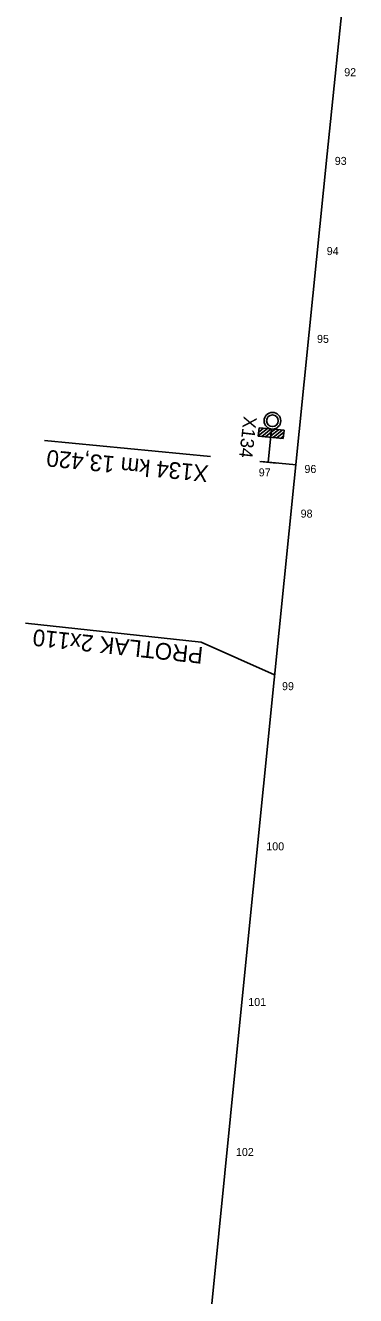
# Model space of a CAD drawing. Extents: x -743397 to -742769, y -1127804 to -1126284.
# Drawn here: x -743366.8 to -743317.3, y -1127613.8 to -1127423.3 of the extents above; entities that cross this region are included whole.
import ezdxf

# ---------------------------------------------------------------- set-up
doc = ezdxf.new("R2010")
doc.units = 0
for name, color, linetype in [('_Zabezpečovací zařízení', 7, 'Continuous'), ('_Zabezpečovací zařízení_trasa', 7, 'Continuous'), ('křížky', 7, 'Continuous'), ('Nový stav', 7, 'Continuous'), ('Vrstva 60', 7, 'Continuous')]:
    doc.layers.add(name, color=color, linetype=linetype)

# ---------------------------------------------------------------- blocks, each defined once
blk = doc.blocks.new('POINT_DISPLAY')
blk.add_line((0, 0), (0, 0))

msp = doc.modelspace()

# ---------------------------------------------------------------- linework, layer by layer
at = {"layer": '_Zabezpečovací zařízení'}
for p, q in [((-743331.88, -1127484.91), (-743331.75, -1127483.67)), ((-743331.88, -1127484.9), (-743330.52, -1127483.8)), ((-743331.82, -1127484.34), (-743331.08, -1127483.74)), ((-743331.76, -1127483.78), (-743331.64, -1127483.68)), ((-743331.75, -1127483.67), (-743328.02, -1127484.05)), ((-743331.34, -1127484.97), (-743329.96, -1127483.85)), ((-743330.4, -1127488.84), (-743329.89, -1127483.86)), ((-743328.15, -1127485.3), (-743331.88, -1127484.91)), ((-743330.78, -1127485.03), (-743329.94, -1127484.34)), ((-743330.22, -1127485.08), (-743330, -1127484.9)), ((-743330, -1127484.9), (-743328.85, -1127483.97)), ((-743329.94, -1127484.34), (-743329.41, -1127483.91)), ((-743329.66, -1127485.14), (-743328.29, -1127484.03)), ((-743329.1, -1127485.2), (-743328.05, -1127484.35)), ((-743328.54, -1127485.26), (-743328.11, -1127484.91)), ((-743328.02, -1127484.05), (-743328.15, -1127485.3)), ((-743329.16, -1127488.96), (-743331.64, -1127488.71))]:
    msp.add_line(p, q, dxfattribs=at)
for radius in [1.25, 0.875]:
    msp.add_circle((-743329.76, -1127482.62), radius, dxfattribs=at)
at = {"layer": '_Zabezpečovací zařízení_trasa'}
for points in [[(-743318.79, -1127415.84), (-743321.57, -1127442.6), (-743324.27, -1127469.35), (-743329.51, -1127521.46), (-743334.23, -1127568.82), (-743338.71, -1127613.56), (-743341.47, -1127641), (-743342.85, -1127654.73), (-743344.22, -1127668.45), (-743346.84, -1127694.61), (-743348.17, -1127707.68), (-743349.5, -1127720.75), (-743351.96, -1127744.53), (-743354.76, -1127768.22), (-743358.32, -1127790.48), (-743359.2, -1127794.79), (-743358.15, -1127794.97)], [(-743331.4, -1127488.73), (-743326.22, -1127489.25)]]:
    msp.add_lwpolyline(points, dxfattribs=at)
at = {"layer": 'Nový stav'}
for p, q in [((-743339.05, -1127488), (-743363.93, -1127485.56)), ((-743339.05, -1127488), (-743363.93, -1127485.56)), ((-743340.45, -1127515.81), (-743366.81, -1127512.98)), ((-743340.45, -1127515.81), (-743366.81, -1127512.98)), ((-743329.44, -1127520.71), (-743340.45, -1127515.81)), ((-743329.44, -1127520.71), (-743340.45, -1127515.81))]:
    msp.add_line(p, q, dxfattribs=at)
at = {"layer": 'Vrstva 60'}
for p, q in [((-743320.18, -1127429.22), (-743320.18, -1127429.22)), ((-743321.57, -1127442.6), (-743321.57, -1127442.6)), ((-743322.92, -1127455.97), (-743322.92, -1127455.97)), ((-743324.27, -1127469.35), (-743324.27, -1127469.35)), ((-743330.4, -1127488.84), (-743330.4, -1127488.84)), ((-743326.22, -1127489.25), (-743326.22, -1127489.25)), ((-743326.89, -1127495.41), (-743326.89, -1127495.41)), ((-743329.51, -1127521.46), (-743329.51, -1127521.46)), ((-743331.87, -1127545.14), (-743331.87, -1127545.14)), ((-743334.23, -1127568.82), (-743334.23, -1127568.82)), ((-743336.47, -1127591.19), (-743336.47, -1127591.19)), ((-743338.71, -1127613.56), (-743338.71, -1127613.56))]:
    msp.add_line(p, q, dxfattribs=at)

# ---------------------------------------------------------------- block references
at = {"layer": 'křížky', "xscale": 10, "yscale": 10, "rotation": 61.14491455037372}
for p in [(-743320.18, -1127429.22), (-743321.57, -1127442.6), (-743322.92, -1127455.97), (-743324.27, -1127469.35), (-743330.4, -1127488.84), (-743326.22, -1127489.25), (-743326.89, -1127495.41), (-743329.51, -1127521.46), (-743331.87, -1127545.14), (-743334.23, -1127568.82), (-743336.47, -1127591.19), (-743338.71, -1127613.56)]:
    msp.add_blockref('POINT_DISPLAY', p, dxfattribs=at)

# ---------------------------------------------------------------- texts
at = {"layer": '_Zabezpečovací zařízení'}
msp.add_text('X134', height=2, rotation=263.5157, dxfattribs=at).set_placement((-743334.07, -1127481.88))
at = {"layer": 'Nový stav'}
for s, rotation, p in [('X134 km 13,420', 174.395, (-743339.28, -1127489.34)), ('X134 km 13,420', 174.395, (-743339.28, -1127489.34)), ('PROTLAK 2x110', 173.8668, (-743340.06, -1127516.59)), ('PROTLAK 2x110', 173.8668, (-743340.06, -1127516.59))]:
    msp.add_text(s, height=2.5, rotation=rotation, dxfattribs=at).set_placement(p)
at = {"layer": 'Vrstva 60'}
for s, p in [('92', (-743318.99, -1127430.95)), ('93', (-743320.41, -1127444.25)), ('94', (-743321.61, -1127457.77)), ('95', (-743323.07, -1127470.94)), ('96', (-743324.96, -1127490.45)), ('97', (-743331.81, -1127490.96)), ('98', (-743325.53, -1127497.14)), ('99', (-743328.32, -1127523.02)), ('100', (-743330.68, -1127547.04)), ('101', (-743333.38, -1127570.38)), ('102', (-743335.23, -1127592.88))]:
    msp.add_text(s, height=1.2, dxfattribs=at).set_placement(p)

doc.saveas('drawing.dxf')
